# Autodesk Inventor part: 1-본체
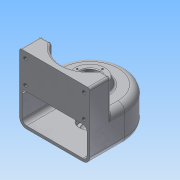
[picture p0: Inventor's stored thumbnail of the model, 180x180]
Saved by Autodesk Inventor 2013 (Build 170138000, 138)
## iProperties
Created: 2015-02
Part Number: 1-본체
Material: 알루미늄 6061
Document SubType Name: Modeling
Designer: Administrator
Density: 2.40731 g/cm^3
Mass: 511.028 g
Surface Area: 707.316 cm^2
Volume: 212.281 cm^3
Author: Administrator
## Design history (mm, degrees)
sketch "스케치1"
  geometry: L1 (-50, -50)-(50, -50); L2 (-50, 0)-(-50, -50); L3 (50, 0)-(50, -50); A1 r 50 centre (0, 0) between (-50, 0) and (50, 0); 1 further point
  constraints: 6 end point, 2 point on circle, 2 tangent, 1 centre point, 1 coincident, 1 horizontal, 1 parallel, 1 perpendicular
  dimensions: "d0" = 50 radius of A1; "d2" = 50 distance from line of L1 point (0, 0)
extrude "돌출1" new body sketch "스케치1" distance "d3" = 50; taper "d4" = 0 deg
feature "쉘1" dims "d5" = 4
fillet "모깎기1" dims "d10" = 10
node "작업 평면1"
sketch "스케치2"
  geometry: L1 (-40, -50)-(40, -50) reference; L2 (-40, -50)-(-50, -50) reference; L3 (50, -50)-(40, -50) reference; L4 (-50, -50)-(-50, -20); L5 (-50, -20)-(-34.641, -20); L6 (50, -50)-(50, -20); L7 (34.641, -20)-(50, -20); L8 (-50, -50)-(50, -50); A1 r 40 centre (0, 0) between (-34.641, -20) and (34.641, -20); 1 further point
  constraints: 10 end point, 4 perpendicular, 2 point on circle, 1 centre point, 1 coincident, 1 parallel
  dimensions: "d7" = 40 radius of A1; "d11" = 30 distance between parallel lines of L1 L5; "d12" = 30 distance between parallel lines of L1 L7
extrude "돌출2" join sketch "스케치2" stored distance "d13" = 86; taper "d14" = 0 deg
sketch "스케치3"
  geometry: C1 r 25 at (0, 0); A1 r 40 centre (0, 0) between (-34.641, -20) and (34.641, -20) reference; A2 r 40 centre (0, 0) between (40, 0) and (-40, 0) reference
  constraints: 2 coincident, 1 centre point
  dimensions: "d15" = 50 diameter of C1
extrude "돌출3" join sketch "스케치3" distance "d17" = 10; taper "d18" = -20 deg
sketch "스케치4"
  geometry: C1 r 20 at (0, 0); A1 r 40 centre (0, 0) between (40, 0) and (-40, 0) reference
  constraints: 1 centre point, 1 coincident
  dimensions: "d19" = 40 diameter of C1
extrude "돌출4" join sketch "스케치4" distance "d21" = 9; taper "d22" = 0 deg
hole "구멍1" diameter "d25" = 20; stored, may be unused: countersink angle "d29" = 90 deg, drill point angle "d31" = 118 deg; dims "d26" = 6, "d27" = 28, "d28" = 10, "d30" = 8, "d32" = 10, "d33" = 10
hole "구멍2" diameter "d36" = 20; stored, may be unused: countersink angle "d40" = 90 deg, drill point angle "d42" = 0 deg; dims "d34" = 10, "d35" = 10, "d37" = 6, "d38" = 28, "d39" = 8, "d41" = 10
sketch "스케치5"
  geometry: C1 r 14 at (0, 0) reference; C2 r 21.36 at (0, 0) reference; A1 r 18 centre (0, 0) between (0, 18) and (18, 0); 2 further points
  constraints: 4 point on circle, 2 horizontal alignment, 2 vertical alignment, 1 centre point, 1 coincident
  dimensions: "d43" = 36 diameter of A1
hole "구멍3" sketch "스케치5" at (0, 18), (18, 0), (-18, 0), (0, -18) diameter "d45" = 2.459; stored, may be unused: countersink angle "d49" = 90 deg, drill point angle "d51" = 118 deg; dims "d46" = 6, "d47" = 28, "d48" = 8, "d50" = 9
sketch "스케치6"
  geometry: L1 (0, 0)-(80, 0) reference; L2 (-10, 95)-(90, 95) reference; L3 (-1.75, 86)-(81.75, 86); L4 (81.75, 86)-(81.75, 53); L5 (81.75, 53)-(-1.75, 53); L6 (-1.75, 53)-(-1.75, 86); L7 (-1.75, 86)-(81.75, 53); L8 (81.75, 86)-(-1.75, 53); 8 further points
  constraints: 12 end point, 4 coincident, 4 midpoint, 2 parallel, 1 horizontal, 1 perpendicular, 1 vertical alignment
  dimensions: "d52" = 33 distance of L5.end L3.start; "d54" = 83.5 distance of L3.start L3.end; "d55" = 9 distance between parallel lines of L3 L2
hole "구멍4" sketch "스케치6" at (-1.75, 86), (81.75, 86), (81.75, 53), (-1.75, 53) diameter "d56" = 5.134; stored, may be unused: countersink angle "d60" = 90 deg, drill point angle "d62" = 118 deg; dims "d57" = 10, "d58" = 28, "d59" = 8, "d61" = 13
fillet "모깎기2" dims "d63" = 6, "d64" = 0.3, "d65" = 3
fillet "모깎기3" dims "d66" = 3
fillet "모깎기4" dims "d67" = 3
fillet "모깎기5" dims "d68" = 3
chamfer "모따기1" distance "d69" = 1; stored, may be unused: second distance "d70" = 2, angle "d71" = 45 deg
node "작업 평면2"
sketch "스케치7"
  geometry: L1 (40, 0)-(-40, 0) reference; 3 further points
  constraints: 1 midpoint, 1 vertical alignment, 1 other
  dimensions: "d72" = 25 distance from line of L1 point (0, 25)
feature "엠보싱1" sketch "스케치7" dims "d0" = 50, "d2" = 50, "d7" = 40, "d11" = 30, "d12" = 30, "d73" = 0.5, "d74" = 0
fillet "모깎기6" dims "d75" = 3
node "솔리드1"
other parameters: "d6" = 45
